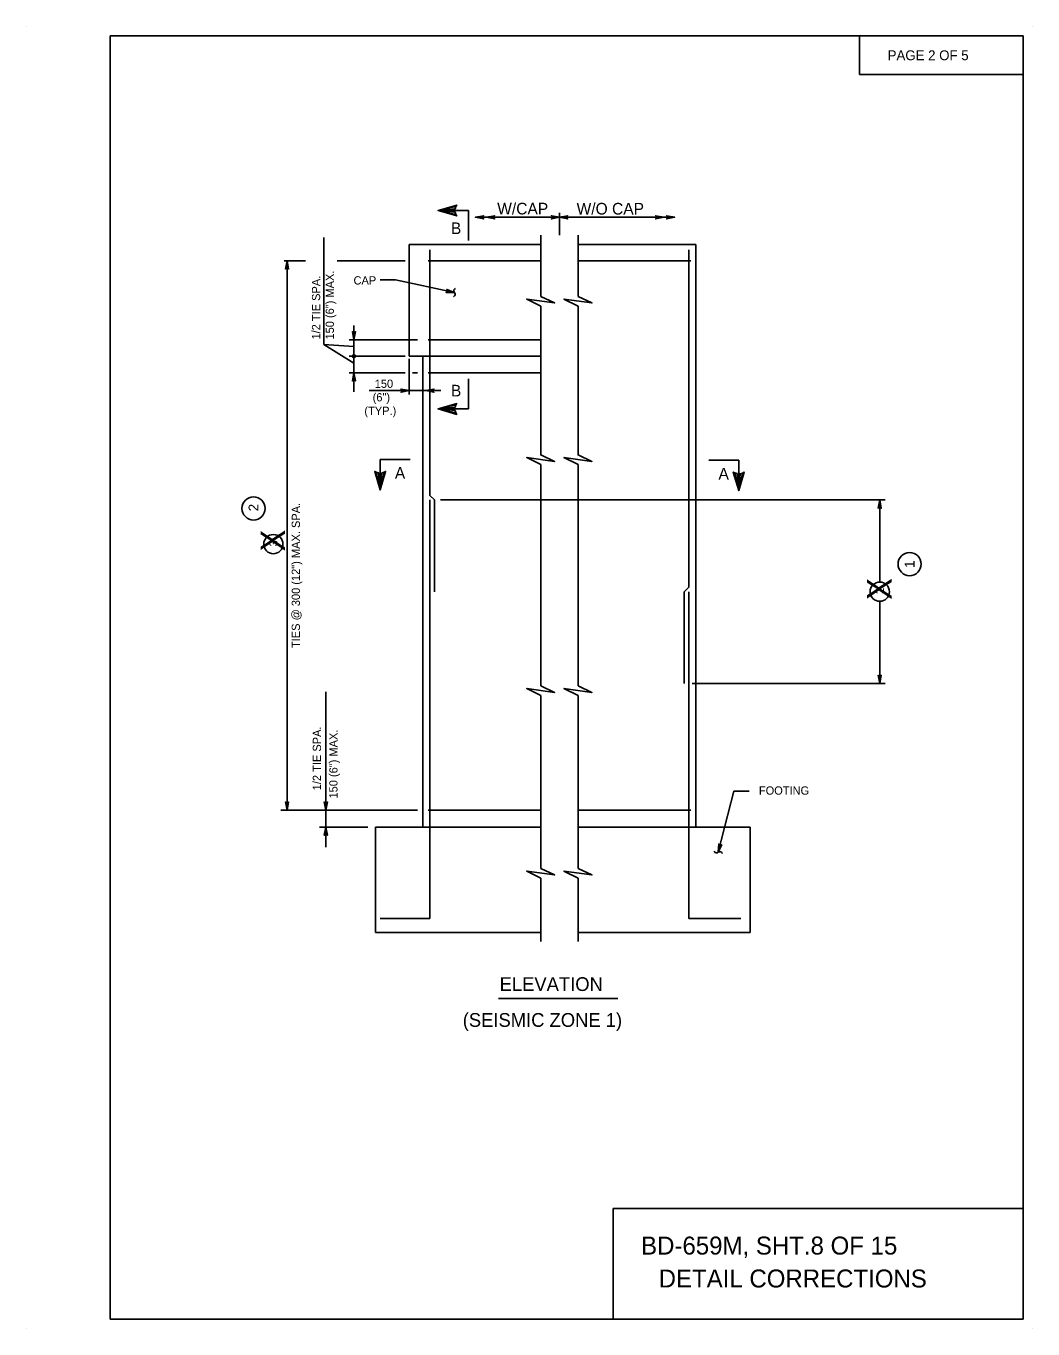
# Model space of a CAD drawing. Extents: x 646165 to 651486, y 296916 to 299292.
# Drawn here: x 646531 to 646897.2, y 298728.6 to 299202.3 of the extents above; entities that cross this region are included whole.
import ezdxf

# ---------------------------------------------------------------- set-up
doc = ezdxf.new("R2010")
doc.units = 0
for name, color, linetype in [('1', 7, 'Continuous'), ('2', 7, 'Continuous'), ('51', 7, 'Continuous'), ('52', 7, 'Continuous'), ('53', 7, 'Continuous'), ('54', 7, 'Continuous'), ('57', 7, 'Continuous')]:
    doc.layers.add(name, color=color, linetype=linetype)

msp = doc.modelspace()

# ---------------------------------------------------------------- linework, layer by layer
at = {"layer": '1'}
for p, q in [((646680.86, 299135.26), (646691.93, 299135.26)), ((646691.93, 299135.26), (646691.93, 299124.34)), ((646691.93, 299063.07), (646691.93, 299073.99)), ((646680.86, 299063.07), (646691.93, 299063.07)), ((646659.78, 299044.71), (646670.7, 299044.71)), ((646659.78, 299033.65), (646659.78, 299044.71)), ((646790.19, 299044.45), (646779.26, 299044.45)), ((646790.19, 299033.38), (646790.19, 299044.45))]:
    msp.add_line(p, q, dxfattribs=at)
for points in [[(646687.28, 299133.79), (646687.04, 299134.64), (646680.86, 299135.26), (646687.28, 299133.79), (646687.61, 299133.27), (646680.86, 299135.26), (646687.04, 299135.82), (646687.26, 299136.65), (646680.86, 299135.26), (646687.61, 299137.21), (646687.26, 299136.65)], [(646687.28, 299064.54), (646687.04, 299063.69), (646680.86, 299063.07), (646687.28, 299064.54), (646687.61, 299065.06), (646680.86, 299063.07), (646687.04, 299062.51), (646687.26, 299061.68), (646680.86, 299063.07), (646687.61, 299061.12), (646687.26, 299061.68)], [(646661.25, 299040.07), (646660.4, 299039.83), (646659.78, 299033.65), (646661.25, 299040.07), (646661.77, 299040.4), (646659.78, 299033.65), (646659.22, 299039.82), (646658.39, 299040.05), (646659.78, 299033.65), (646657.83, 299040.4), (646658.39, 299040.05)], [(646788.71, 299039.8), (646789.56, 299039.56), (646790.19, 299033.38), (646788.71, 299039.8), (646788.2, 299040.13), (646790.19, 299033.38), (646790.74, 299039.55), (646791.58, 299039.78), (646790.19, 299033.38), (646792.14, 299040.13), (646791.58, 299039.78)]]:
    msp.add_lwpolyline(points, dxfattribs=at)
at = {"layer": '2'}
for p, q in [((646561.63, 298732.16), (646561.63, 299198.75)), ((646893.63, 299198.75), (646561.63, 299198.75)), ((646834.06, 299184.66), (646834.06, 299198.75)), ((646893.63, 298732.16), (646893.63, 299198.75)), ((646893.63, 299184.66), (646834.06, 299184.66)), ((646893.63, 298772.44), (646744.53, 298772.44)), ((646744.53, 298732.16), (646744.53, 298772.44)), ((646893.63, 298732.16), (646561.63, 298732.16))]:
    msp.add_line(p, q, dxfattribs=at)
at = {"layer": '51'}
for p, q in [((646670.35, 299122.9), (646670.35, 299082.23)), ((646670.35, 299122.9), (646718.27, 299122.9)), ((646731.79, 299122.9), (646774.53, 299122.9)), ((646774.53, 299122.9), (646774.53, 298911.08)), ((646670.35, 299082.23), (646718.27, 299082.23)), ((646675.35, 299082.23), (646675.35, 298911.08)), ((646658.08, 298911.08), (646718.27, 298911.08)), ((646658.08, 298911.08), (646658.08, 298872.74)), ((646731.79, 298911.08), (646794.3, 298911.08)), ((646794.3, 298911.08), (646794.3, 298872.74)), ((646658.08, 298872.74), (646718.27, 298872.74)), ((646731.79, 298872.74), (646794.3, 298872.74))]:
    msp.add_line(p, q, dxfattribs=at)
at = {"layer": '52'}
for p, q in [((646694.45, 299132.75), (646725.03, 299132.75)), ((646725.03, 299126.32), (646725.03, 299134.34)), ((646725.03, 299132.75), (646766.91, 299132.75)), ((646718.27, 299126.23), (646718.27, 299103.97)), ((646731.79, 299126.23), (646731.79, 299103.97)), ((646639.27, 299086.57), (646639.27, 299125.41)), ((646624.83, 299116.9), (646632.64, 299116.9)), ((646625.93, 299116.9), (646625.93, 298917.23)), ((646644.12, 299116.9), (646668.9, 299116.9)), ((646659.83, 299110.01), (646665.41, 299110.01)), ((646686.8, 299105.36), (646665.41, 299110.01)), ((646718.27, 299100.47), (646718.27, 299046.34)), ((646731.79, 299100.47), (646731.79, 299046.34)), ((646650.23, 299093.48), (646650.23, 299069.36)), ((646648.57, 299088.23), (646673.35, 299088.23)), ((646639.27, 299086.57), (646650.23, 299079.72)), ((646639.27, 299086.57), (646650.23, 299085.73)), ((646648.57, 299082.23), (646668.9, 299082.23)), ((646670.35, 299081.3), (646670.35, 299068.39)), ((646648.57, 299076.23), (646668.9, 299076.23)), ((646671.57, 299076.23), (646673.35, 299076.23)), ((646655.81, 299069.73), (646681.84, 299069.73)), ((646718.27, 299042.84), (646718.27, 298962.39)), ((646731.79, 299042.84), (646731.79, 298962.39)), ((646681.73, 299029.99), (646774.67, 299029.99)), ((646750.44, 299029.99), (646843.38, 299029.99)), ((646841.46, 299000.15), (646841.46, 299029.99)), ((646841.46, 298963.32), (646841.46, 298993.15)), ((646640.03, 298960.2), (646640.03, 298903.76)), ((646773.2, 298963.32), (646843.38, 298963.32)), ((646775.16, 298963.32), (646774.67, 298963.32)), ((646718.27, 298958.87), (646718.27, 298896.02)), ((646731.79, 298958.87), (646731.79, 298896.04)), ((646788.39, 298924.15), (646782.73, 298901.91)), ((646788.39, 298924.15), (646793.97, 298924.15)), ((646623.71, 298917.23), (646673.35, 298917.23)), ((646637.69, 298911.08), (646655.27, 298911.08)), ((646718.27, 298892.52), (646718.27, 298869.47)), ((646731.79, 298892.52), (646731.79, 298869.47))]:
    msp.add_line(p, q, dxfattribs=at)
for points in [[(646694.45, 299132.75), (646697.43, 299133.31), (646697.2, 299133.15), (646697.08, 299132.95), (646697.05, 299132.75), (646697.08, 299132.55), (646697.2, 299132.35), (646697.43, 299132.19), (646694.45, 299132.75), (646697.2, 299132.35), (646697.08, 299132.55), (646694.45, 299132.75), (646697.05, 299132.75), (646697.08, 299132.95), (646694.45, 299132.75), (646697.2, 299133.15)], [(646698.45, 299132.75), (646701.43, 299133.31), (646701.2, 299133.15), (646701.08, 299132.95), (646701.05, 299132.75), (646701.08, 299132.55), (646701.2, 299132.35), (646701.43, 299132.19), (646698.45, 299132.75), (646701.2, 299132.35), (646701.08, 299132.55), (646698.45, 299132.75), (646701.05, 299132.75), (646701.08, 299132.95), (646698.45, 299132.75), (646701.2, 299133.15)], [(646725.03, 299132.75), (646722.05, 299132.19), (646722.28, 299132.35), (646722.4, 299132.55), (646722.43, 299132.75), (646722.4, 299132.95), (646722.28, 299133.15), (646722.05, 299133.31), (646725.03, 299132.75), (646722.28, 299133.15), (646722.4, 299132.95), (646725.03, 299132.75), (646722.43, 299132.75), (646722.4, 299132.55), (646725.03, 299132.75), (646722.28, 299132.35)], [(646725.03, 299132.75), (646722.05, 299132.19), (646722.28, 299132.35), (646722.4, 299132.55), (646722.43, 299132.75), (646722.4, 299132.95), (646722.28, 299133.15), (646722.05, 299133.31), (646725.03, 299132.75), (646722.28, 299133.15), (646722.4, 299132.95), (646725.03, 299132.75), (646722.43, 299132.75), (646722.4, 299132.55), (646725.03, 299132.75), (646722.28, 299132.35)], [(646725.03, 299132.75), (646728.02, 299133.31), (646727.79, 299133.15), (646727.67, 299132.95), (646727.63, 299132.75), (646727.67, 299132.55), (646727.79, 299132.35), (646728.02, 299132.19), (646725.03, 299132.75), (646727.79, 299132.35), (646727.67, 299132.55), (646725.03, 299132.75), (646727.63, 299132.75), (646727.67, 299132.95), (646725.03, 299132.75), (646727.79, 299133.15)], [(646762.91, 299132.75), (646759.93, 299132.19), (646760.16, 299132.35), (646760.27, 299132.55), (646760.31, 299132.75), (646760.27, 299132.95), (646760.16, 299133.15), (646759.93, 299133.31), (646762.91, 299132.75), (646760.16, 299133.15), (646760.27, 299132.95), (646762.91, 299132.75), (646760.31, 299132.75), (646760.27, 299132.55), (646762.91, 299132.75), (646760.16, 299132.35)], [(646766.91, 299132.75), (646763.93, 299132.19), (646764.16, 299132.35), (646764.27, 299132.55), (646764.31, 299132.75), (646764.27, 299132.95), (646764.16, 299133.15), (646763.93, 299133.31), (646766.91, 299132.75), (646764.16, 299133.15), (646764.27, 299132.95), (646766.91, 299132.75), (646764.31, 299132.75), (646764.27, 299132.55), (646766.91, 299132.75), (646764.16, 299132.35)], [(646625.93, 299116.9), (646626.49, 299113.91), (646626.41, 299114.03), (646626.33, 299114.14), (646626.23, 299114.2), (646626.13, 299114.26), (646626.03, 299114.28), (646625.93, 299114.3), (646625.83, 299114.28), (646625.73, 299114.26), (646625.63, 299114.2), (646625.53, 299114.14), (646625.45, 299114.03), (646625.37, 299113.91), (646625.93, 299116.9), (646625.45, 299114.03), (646625.53, 299114.14), (646625.93, 299116.9), (646625.63, 299114.2), (646625.73, 299114.26), (646625.93, 299116.9), (646625.83, 299114.28), (646625.93, 299114.3), (646625.93, 299116.9), (646626.03, 299114.28), (646626.13, 299114.26), (646625.93, 299116.9), (646626.23, 299114.2), (646626.33, 299114.14), (646625.93, 299116.9), (646626.41, 299114.03)], [(646686.8, 299105.36), (646683.77, 299105.45), (646684.03, 299105.56), (646684.19, 299105.73), (646684.26, 299105.92), (646684.27, 299106.12), (646684.2, 299106.34), (646684.01, 299106.54), (646686.8, 299105.36), (646684.2, 299106.34), (646684.27, 299106.12), (646686.8, 299105.36), (646684.26, 299105.92), (646684.19, 299105.73), (646686.8, 299105.36), (646684.03, 299105.56)], [(646718.27, 299100.47), (646713.09, 299103.01), (646723.24, 299101.63), (646718.27, 299103.99)], [(646731.79, 299100.47), (646726.61, 299103.01), (646736.76, 299101.63), (646731.79, 299103.99)], [(646650.23, 299088.23), (646649.67, 299091.21), (646649.75, 299091.1), (646649.83, 299090.98), (646649.93, 299090.92), (646650.03, 299090.86), (646650.13, 299090.85), (646650.23, 299090.83), (646650.33, 299090.85), (646650.43, 299090.86), (646650.53, 299090.92), (646650.63, 299090.98), (646650.71, 299091.1), (646650.79, 299091.21), (646650.23, 299088.23), (646650.71, 299091.1), (646650.63, 299090.98), (646650.23, 299088.23), (646650.53, 299090.92), (646650.43, 299090.86), (646650.23, 299088.23), (646650.33, 299090.85), (646650.23, 299090.83), (646650.23, 299088.23), (646650.13, 299090.85), (646650.03, 299090.86), (646650.23, 299088.23), (646649.93, 299090.92), (646649.83, 299090.98), (646650.23, 299088.23), (646649.75, 299091.1)], [(646650.23, 299076.23), (646650.79, 299073.25), (646650.71, 299073.36), (646650.63, 299073.48), (646650.53, 299073.54), (646650.43, 299073.6), (646650.33, 299073.61), (646650.23, 299073.63), (646650.13, 299073.61), (646650.03, 299073.6), (646649.93, 299073.54), (646649.83, 299073.48), (646649.75, 299073.36), (646649.67, 299073.25), (646650.23, 299076.23), (646649.75, 299073.36), (646649.83, 299073.48), (646650.23, 299076.23), (646649.93, 299073.54), (646650.03, 299073.6), (646650.23, 299076.23), (646650.13, 299073.61), (646650.23, 299073.63), (646650.23, 299076.23), (646650.33, 299073.61), (646650.43, 299073.6), (646650.23, 299076.23), (646650.53, 299073.54), (646650.63, 299073.48), (646650.23, 299076.23), (646650.71, 299073.36)], [(646670.35, 299069.73), (646667.37, 299070.29), (646667.48, 299070.21), (646667.6, 299070.13), (646667.66, 299070.03), (646667.72, 299069.93), (646667.73, 299069.83), (646667.75, 299069.73), (646667.73, 299069.63), (646667.72, 299069.53), (646667.66, 299069.43), (646667.6, 299069.33), (646667.48, 299069.25), (646667.37, 299069.17), (646670.35, 299069.73), (646667.48, 299069.25), (646667.6, 299069.33), (646670.35, 299069.73), (646667.66, 299069.43), (646667.72, 299069.53), (646670.35, 299069.73), (646667.73, 299069.63), (646667.75, 299069.73), (646670.35, 299069.73), (646667.73, 299069.83), (646667.72, 299069.93), (646670.35, 299069.73), (646667.66, 299070.03), (646667.6, 299070.13), (646670.35, 299069.73), (646667.48, 299070.21)], [(646676.35, 299069.73), (646679.33, 299070.29), (646679.22, 299070.21), (646679.1, 299070.13), (646679.04, 299070.03), (646678.98, 299069.93), (646678.97, 299069.83), (646678.95, 299069.73), (646678.97, 299069.63), (646678.98, 299069.53), (646679.04, 299069.43), (646679.1, 299069.33), (646679.22, 299069.25), (646679.33, 299069.17), (646676.35, 299069.73), (646679.22, 299069.25), (646679.1, 299069.33), (646676.35, 299069.73), (646679.04, 299069.43), (646678.98, 299069.53), (646676.35, 299069.73), (646678.97, 299069.63), (646678.95, 299069.73), (646676.35, 299069.73), (646678.97, 299069.83), (646678.98, 299069.93), (646676.35, 299069.73), (646679.04, 299070.03), (646679.1, 299070.13), (646676.35, 299069.73), (646679.22, 299070.21)], [(646718.27, 299042.84), (646713.09, 299045.38), (646723.24, 299044), (646718.27, 299046.36)], [(646731.79, 299042.84), (646726.61, 299045.38), (646736.76, 299044), (646731.79, 299046.36)], [(646841.46, 299029.99), (646842.02, 299027), (646841.94, 299027.12), (646841.86, 299027.23), (646841.76, 299027.29), (646841.66, 299027.35), (646841.56, 299027.37), (646841.46, 299027.39), (646841.36, 299027.37), (646841.26, 299027.35), (646841.16, 299027.29), (646841.06, 299027.23), (646840.98, 299027.12), (646840.9, 299027), (646841.46, 299029.99), (646840.98, 299027.12), (646841.06, 299027.23), (646841.46, 299029.99), (646841.16, 299027.29), (646841.26, 299027.35), (646841.46, 299029.99), (646841.36, 299027.37), (646841.46, 299027.39), (646841.46, 299029.99), (646841.56, 299027.37), (646841.66, 299027.35), (646841.46, 299029.99), (646841.76, 299027.29), (646841.86, 299027.23), (646841.46, 299029.99), (646841.94, 299027.12)], [(646841.46, 298963.32), (646840.9, 298966.3), (646840.98, 298966.19), (646841.06, 298966.07), (646841.16, 298966.01), (646841.26, 298965.95), (646841.36, 298965.94), (646841.46, 298965.92), (646841.56, 298965.94), (646841.66, 298965.95), (646841.76, 298966.01), (646841.86, 298966.07), (646841.94, 298966.19), (646842.02, 298966.3), (646841.46, 298963.32), (646841.94, 298966.19), (646841.86, 298966.07), (646841.46, 298963.32), (646841.76, 298966.01), (646841.66, 298965.95), (646841.46, 298963.32), (646841.56, 298965.94), (646841.46, 298965.92), (646841.46, 298963.32), (646841.36, 298965.94), (646841.26, 298965.95), (646841.46, 298963.32), (646841.16, 298966.01), (646841.06, 298966.07), (646841.46, 298963.32), (646840.98, 298966.19)], [(646718.27, 298958.87), (646713.09, 298961.41), (646723.24, 298960.03), (646718.27, 298962.39)], [(646731.79, 298958.87), (646726.61, 298961.41), (646736.76, 298960.03), (646731.79, 298962.39)], [(646625.93, 298917.23), (646625.37, 298920.22), (646625.45, 298920.1), (646625.53, 298919.99), (646625.63, 298919.93), (646625.73, 298919.87), (646625.83, 298919.85), (646625.93, 298919.83), (646626.03, 298919.85), (646626.13, 298919.87), (646626.23, 298919.93), (646626.33, 298919.99), (646626.41, 298920.1), (646626.49, 298920.22), (646625.93, 298917.23), (646626.41, 298920.1), (646626.33, 298919.99), (646625.93, 298917.23), (646626.23, 298919.93), (646626.13, 298919.87), (646625.93, 298917.23), (646626.03, 298919.85), (646625.93, 298919.83), (646625.93, 298917.23), (646625.83, 298919.85), (646625.73, 298919.87), (646625.93, 298917.23), (646625.63, 298919.93), (646625.53, 298919.99), (646625.93, 298917.23), (646625.45, 298920.1)], [(646640.03, 298917.23), (646639.48, 298920.22), (646639.56, 298920.1), (646639.63, 298919.99), (646639.73, 298919.93), (646639.83, 298919.87), (646639.93, 298919.85), (646640.03, 298919.83), (646640.13, 298919.85), (646640.23, 298919.87), (646640.33, 298919.93), (646640.43, 298919.99), (646640.51, 298920.1), (646640.59, 298920.22), (646640.03, 298917.23), (646640.51, 298920.1), (646640.43, 298919.99), (646640.03, 298917.23), (646640.33, 298919.93), (646640.23, 298919.87), (646640.03, 298917.23), (646640.13, 298919.85), (646640.03, 298919.83), (646640.03, 298917.23), (646639.93, 298919.85), (646639.83, 298919.87), (646640.03, 298917.23), (646639.73, 298919.93), (646639.63, 298919.99), (646640.03, 298917.23), (646639.56, 298920.1)], [(646640.03, 298911.08), (646640.59, 298908.09), (646640.51, 298908.21), (646640.43, 298908.32), (646640.33, 298908.38), (646640.23, 298908.44), (646640.13, 298908.46), (646640.03, 298908.48), (646639.93, 298908.46), (646639.83, 298908.44), (646639.73, 298908.38), (646639.63, 298908.32), (646639.56, 298908.21), (646639.48, 298908.09), (646640.03, 298911.08), (646639.56, 298908.21), (646639.63, 298908.32), (646640.03, 298911.08), (646639.73, 298908.38), (646639.83, 298908.44), (646640.03, 298911.08), (646639.93, 298908.46), (646640.03, 298908.48), (646640.03, 298911.08), (646640.13, 298908.46), (646640.23, 298908.44), (646640.03, 298911.08), (646640.33, 298908.38), (646640.43, 298908.32), (646640.03, 298911.08), (646640.51, 298908.21)], [(646782.73, 298901.91), (646782.92, 298904.94), (646782.97, 298904.81), (646783.02, 298904.68), (646783.1, 298904.6), (646783.19, 298904.52), (646783.28, 298904.47), (646783.37, 298904.43), (646783.47, 298904.43), (646783.57, 298904.42), (646783.68, 298904.45), (646783.8, 298904.48), (646783.9, 298904.57), (646784.01, 298904.67), (646782.73, 298901.91), (646783.9, 298904.57), (646783.8, 298904.48), (646782.73, 298901.91), (646783.68, 298904.45), (646783.57, 298904.42), (646782.73, 298901.91), (646783.47, 298904.43), (646783.37, 298904.43), (646782.73, 298901.91), (646783.28, 298904.47), (646783.19, 298904.52), (646782.73, 298901.91), (646783.1, 298904.6), (646783.02, 298904.68), (646782.73, 298901.91), (646782.97, 298904.81)], [(646718.27, 298892.52), (646713.09, 298895.05), (646723.24, 298893.67), (646718.27, 298896.04)], [(646731.79, 298892.52), (646726.61, 298895.05), (646736.76, 298893.67), (646731.79, 298896.04)]]:
    msp.add_lwpolyline(points, dxfattribs=at)
for centre, radius in [((646650.23, 299082.23), 0.533), ((646650.23, 299082.23), 0.267), ((646613.73, 299026.9), 4.2), ((646620.95, 299013.95), 3.5), ((646852.31, 299006.67), 4.2), ((646841.46, 298996.65), 3.5)]:
    msp.add_circle(centre, radius, dxfattribs=at)
for points in [[(646687.17, 299106.88), (646686.53, 299106.13), (646687.08, 299104.58), (646686.49, 299103.84)], [(646784.23, 298901.5), (646783.51, 298902.16), (646781.94, 298901.67), (646781.22, 298902.28)]]:
    msp.add_spline(points, degree=3, dxfattribs=at)
at = {"layer": '53'}
msp.add_line((646702.87, 298848.72), (646746.25, 298848.72), dxfattribs=at)
at = {"layer": '54'}
for p, q in [((646677.18, 299116.9), (646718.27, 299116.9)), ((646677.85, 299120.9), (646677.85, 299031.65)), ((646731.79, 299116.9), (646772.7, 299116.9)), ((646772.03, 299120.9), (646772.03, 298998.32)), ((646677.18, 299088.23), (646718.27, 299088.23)), ((646677.18, 299076.23), (646718.27, 299076.23)), ((646679.52, 299029.99), (646677.85, 299031.65)), ((646677.85, 299029.99), (646677.85, 298877.86)), ((646679.52, 299029.99), (646679.52, 298996.65)), ((646770.36, 298996.65), (646772.03, 298998.32)), ((646770.36, 298996.65), (646770.36, 298963.32)), ((646772.03, 298996.65), (646772.03, 298877.86)), ((646677.18, 298917.23), (646718.27, 298917.23)), ((646731.79, 298917.23), (646772.7, 298917.23)), ((646659.75, 298877.86), (646677.85, 298877.86)), ((646772.03, 298877.86), (646790.96, 298877.86))]:
    msp.add_line(p, q, dxfattribs=at)
at = {"layer": '57'}
for p, q in [((646531.01, 299202.28), (646531.01, 299202.28)), ((646531.01, 299202.28), (646531.01, 299202.28)), ((646897.17, 299202.28), (646897.17, 299202.28)), ((646531.01, 298728.63), (646531.01, 298728.63)), ((646897.17, 298728.63), (646897.17, 298728.63))]:
    msp.add_line(p, q, dxfattribs=at)

# ---------------------------------------------------------------- texts
at = {"layer": '1'}
for s, p in [('W/CAP', (646702.35, 299133.79)), ('W/O CAP', (646731.22, 299133.76)), ('B', (646685.51, 299126.66)), ('B', (646685.51, 299067.62)), ('A', (646665.13, 299037.7)), ('A', (646782.82, 299037.43))]:
    msp.add_text(s, height=4.23, dxfattribs=at).set_placement(p)
at = {"layer": '53'}
for s, height, p in [('PAGE 2 OF 5', 3.6, (646844.34, 299189.85)), ('CAP', 3, (646650.1, 299108.32)), ('150', 3, (646657.81, 299070.75)), ('(6")', 3, (646657.05, 299065.83)), ('(TYP.)', 3, (646654.05, 299060.91)), ('FOOTING', 3, (646797.51, 298922.86)), ('ELEVATION', 5, (646703.23, 298851.49)), ('(SEISMIC ZONE 1)', 5, (646689.81, 298838.45))]:
    msp.add_text(s, height=height, dxfattribs=at).set_placement(p)
for s, height, p in [('150 (6") MAX.', 3, (646642.97, 299088.32)), ('1/2 TIE SPA.', 3, (646637.97, 299088.32)), ('2', 3.6, (646615.53, 299025.88)), ('TIES @ 300 (12") MAX. SPA.', 3, (646630.61, 298976.17)), ('3', 3, (646622.45, 299013.1)), ('1', 3.6, (646854.11, 299005.31)), ('2', 3, (646842.96, 298995.8)), ('1/2 TIE SPA.', 3, (646638.27, 298924.45)), ('150 (6") MAX.', 3, (646644.27, 298921.45))]:
    msp.add_text(s, height=height, rotation=90, dxfattribs=at).set_placement(p)
at = {"layer": '57'}
for p in [(646625.23, 299011.24), (646845.83, 298993.64)]:
    msp.add_text('X', height=8.96, rotation=90, dxfattribs=at).set_placement(p)
for s, p in [('BD-659M, SHT.8 OF 15', (646754.67, 298755.67)), ('DETAIL CORRECTIONS', (646761.05, 298743.7))]:
    msp.add_text(s, height=6.5304, dxfattribs=at).set_placement(p)

doc.saveas('drawing.dxf')
